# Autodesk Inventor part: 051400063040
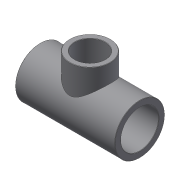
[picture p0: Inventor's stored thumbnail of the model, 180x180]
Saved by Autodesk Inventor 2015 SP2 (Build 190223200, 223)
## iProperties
Created: 2017-10
Part Number: 051400063040
Material: Generic
Description: PLASSON REDUCER TEE - CEMENT PVC 63-40-63
Document SubType Name: Modeling
Designer: KIM
Density: 1 g/cm^3
Appearance: Default
Author: KIM
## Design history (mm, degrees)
derived "051400.ipt"
feature "Solid1::051400.ipt"
feature "Solid2::051400.ipt"
tag "TaggingFeature1"
body "Solid1"
other parameters: "d0" = 144, "d1" = 77, "d2" = 38, "d4" = 63, "d5" = 56.7, "d7" = 0.63, "d8" = 38, "d9" = 60.5, "d12" = 36, "d23" = 26, "d24" = 0.63, "d26" = 0, "d30" = 0, "d32" = 0, "d_" = 63, "E_" = 77, "H_" = 144, "l_" = 38, "Z_" = 14, "l_1" = 26, "Z_1" = 12.5, "H_1" = 99
